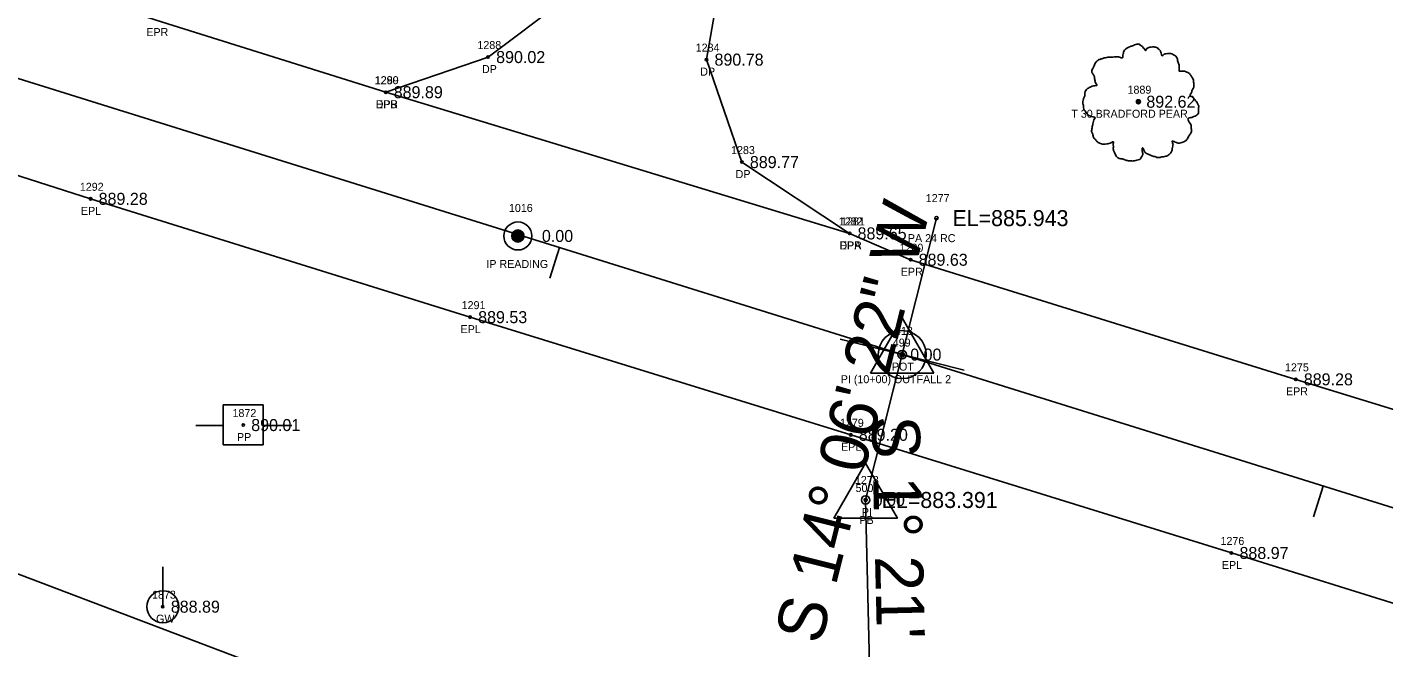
# Model space of a CAD drawing. Extents: x 1448136 to 1453623, y 1125056 to 1128842.
# Drawn here: x 1449466.4 to 1449636, y 1126782.3 to 1126859.8 of the extents above; entities that cross this region are included whole.
import ezdxf

# ---------------------------------------------------------------- set-up
doc = ezdxf.new("R2010")
doc.units = 0
for name, color, linetype in [('RD_EX_DR_Pipe', 7, 'Continuous'), ('RD_EX_DR_Pipe_txCode', 7, 'Continuous'), ('RD_EX_Driveway', 7, 'Continuous'), ('RD_EX_Driveway_txCode', 7, 'Continuous'), ('RD_EX_DV_Prop_txCode', 7, 'Continuous'), ('RD_EX_DV_PropPin', 7, 'Continuous'), ('RD_EX_Road', 7, 'Continuous'), ('RD_EX_Road_txCode', 7, 'Continuous'), ('RD_EX_TX_Driveway_ELEV', 7, 'Continuous'), ('RD_EX_TX_DV_Prop_ELEV', 7, 'Continuous'), ('RD_EX_TX_Road_ELEV', 7, 'Continuous'), ('RD_EX_TX_UT_ELEV', 7, 'Continuous'), ('RD_EX_TX_VEG_ELEV', 7, 'Continuous'), ('RD_EX_UT', 7, 'Continuous'), ('RD_EX_UT_txCode', 7, 'Continuous'), ('RD_EX_VEG', 7, 'Continuous'), ('RD_EX_VEG_txCode', 7, 'Continuous'), ('RD_HC_Cl', 7, 'Continuous'), ('RD_HC_Data', 7, 'Continuous'), ('RD_HC_Data_Tic', 7, 'Continuous'), ('RD_HC_Survey_ELEV', 7, 'Continuous'), ('RD_HC_txCode', 7, 'Continuous'), ('RD_SMD_Locator', 7, 'Continuous'), ('RD_TX_Pipe_ElevEX', 7, 'Continuous')]:
    doc.layers.add(name, color=color, linetype=linetype)

msp = doc.modelspace()

# ---------------------------------------------------------------- linework, layer by layer
at = {"layer": 'RD_EX_DR_Pipe'}
msp.add_line((1449580.07, 1126835.94), (1449571.22, 1126800.73), dxfattribs=at)
at = {"layer": 'RD_EX_Driveway'}
for points in [[(1449544.19, 1126877.39), (1449533.57, 1126863.24), (1449524.04, 1126856.06), (1449511.24, 1126851.67)], [(1449569.21, 1126834.03), (1449555.75, 1126842.94), (1449551.33, 1126855.74), (1449554.29, 1126872.78)]]:
    msp.add_lwpolyline(points, dxfattribs=at)
at = {"layer": 'RD_EX_DV_PropPin'}
for p, q in [((1449527.03, 1126833.51), (1449527.03, 1126833.9)), ((1449527.06, 1126833.41), (1449527.06, 1126834)), ((1449527.1, 1126833.34), (1449527.1, 1126834.08)), ((1449527.13, 1126833.28), (1449527.13, 1126834.13)), ((1449527.17, 1126833.23), (1449527.17, 1126834.18)), ((1449527.2, 1126833.19), (1449527.2, 1126834.22)), ((1449527.24, 1126833.16), (1449527.24, 1126834.26)), ((1449527.27, 1126833.12), (1449527.27, 1126834.29)), ((1449527.31, 1126833.1), (1449527.31, 1126834.32)), ((1449527.34, 1126833.07), (1449527.34, 1126834.34)), ((1449527.38, 1126833.05), (1449527.38, 1126834.36)), ((1449527.41, 1126833.03), (1449527.41, 1126834.38)), ((1449527.45, 1126833.01), (1449527.45, 1126834.4)), ((1449527.48, 1126833), (1449527.48, 1126834.41)), ((1449527.52, 1126832.99), (1449527.52, 1126834.43)), ((1449527.55, 1126832.98), (1449527.55, 1126834.44)), ((1449527.59, 1126832.97), (1449527.59, 1126834.45)), ((1449527.62, 1126832.96), (1449527.62, 1126834.46)), ((1449527.66, 1126832.95), (1449527.66, 1126834.46)), ((1449527.69, 1126832.95), (1449527.69, 1126834.46)), ((1449527.73, 1126832.95), (1449527.73, 1126834.47)), ((1449527.76, 1126832.95), (1449527.76, 1126834.47)), ((1449527.8, 1126832.95), (1449527.8, 1126834.47)), ((1449527.83, 1126832.95), (1449527.83, 1126834.46)), ((1449527.87, 1126832.95), (1449527.87, 1126834.46)), ((1449527.9, 1126832.96), (1449527.9, 1126834.46)), ((1449527.94, 1126832.97), (1449527.94, 1126834.45)), ((1449527.97, 1126832.98), (1449527.97, 1126834.44)), ((1449528.01, 1126832.99), (1449528.01, 1126834.43)), ((1449528.04, 1126833), (1449528.04, 1126834.41)), ((1449528.08, 1126833.01), (1449528.08, 1126834.4)), ((1449528.11, 1126833.03), (1449528.11, 1126834.38)), ((1449528.15, 1126833.05), (1449528.15, 1126834.36)), ((1449528.18, 1126833.07), (1449528.18, 1126834.34)), ((1449528.22, 1126833.1), (1449528.22, 1126834.32)), ((1449528.25, 1126833.12), (1449528.25, 1126834.29)), ((1449528.29, 1126833.16), (1449528.29, 1126834.26)), ((1449528.32, 1126833.19), (1449528.32, 1126834.22)), ((1449528.36, 1126833.23), (1449528.36, 1126834.18)), ((1449528.39, 1126833.28), (1449528.39, 1126834.13)), ((1449528.43, 1126833.34), (1449528.43, 1126834.08)), ((1449528.46, 1126833.41), (1449528.46, 1126834)), ((1449528.5, 1126833.51), (1449528.5, 1126833.9))]:
    msp.add_line(p, q, dxfattribs=at)
for radius in [1.75, 0.761]:
    msp.add_circle((1449527.76, 1126833.71), radius, dxfattribs=at)
at = {"layer": 'RD_EX_Road'}
for points in [[(1450334.81, 1126677.22), (1450288.34, 1126667.77), (1450239.92, 1126662.52), (1450192.72, 1126661.45), (1450145.26, 1126665.09), (1450097.34, 1126672.81), (1450049.7, 1126684.25), (1450007.41, 1126696.7), (1449955.88, 1126712.65), (1449909.23, 1126727.21), (1449862.31, 1126741.85), (1449813.73, 1126756.84), (1449766.18, 1126771.72), (1449717.33, 1126787.19), (1449671.79, 1126801.4), (1449624.98, 1126815.8), (1449576.84, 1126830.74), (1449569.21, 1126834.03), (1449511.24, 1126851.67), (1449482.54, 1126860.68), (1449432.31, 1126877.02)], [(1450340.73, 1126655.01), (1450291.74, 1126645.33), (1450242.07, 1126639.91), (1450191.92, 1126637.95), (1450184.99, 1126636.16), (1450163.38, 1126634.92), (1450141.93, 1126638.08), (1450123.3, 1126641.98), (1450121.61, 1126644.88), (1450093.17, 1126650), (1450044.99, 1126661.93), (1449996.8, 1126675.54), (1449949.24, 1126690.23), (1449901.53, 1126705.51), (1449854.27, 1126720.01), (1449807.04, 1126735.02), (1449759.58, 1126749.86), (1449712.08, 1126764.7), (1449664.51, 1126779.32), (1449616.94, 1126794.11), (1449569.36, 1126808.87), (1449521.79, 1126823.57), (1449474.36, 1126838.35), (1449426.72, 1126853.6)]]:
    msp.add_lwpolyline(points, dxfattribs=at)
at = {"layer": 'RD_EX_UT'}
for p, q in [((1449495.93, 1126812.6), (1449490.93, 1126812.6)), ((1449490.93, 1126812.6), (1449490.93, 1126807.6)), ((1449495.93, 1126807.6), (1449495.93, 1126812.6)), ((1449487.49, 1126810.04), (1449490.96, 1126810.04)), ((1449495.85, 1126810.04), (1449499.49, 1126810.04)), ((1449490.93, 1126807.6), (1449495.93, 1126807.6)), ((1449483.38, 1126787.4), (1449483.38, 1126792.4))]:
    msp.add_line(p, q, dxfattribs=at)
msp.add_circle((1449483.38, 1126787.4), 2, dxfattribs=at)
at = {"layer": 'RD_EX_VEG'}
msp.add_lwpolyline([(1449580.16, 1126756.85), (1449515.49, 1126772.44), (1449452.16, 1126796.48), (1449411.7, 1126813.35), (1449361.89, 1126826.23), (1449322.6, 1126840.71), (1449267.19, 1126862.08), (1449183.91, 1126901.45), (1449150.59, 1126885.87), (1449094.51, 1126880.74), (1449046.23, 1126869.03), (1449021.78, 1126857.03), (1449018.91, 1126811.39)], dxfattribs=at)
for centre, radius in [((1449605.3, 1126850.48), 0.25), ((1449605.29, 1126850.46), 0.0001)]:
    msp.add_circle(centre, radius, dxfattribs=at)
for points in [[(1449605.43, 1126857.65), (1449605.13, 1126857.67), (1449604.81, 1126857.57), (1449604.56, 1126857.47), (1449604.33, 1126857.4), (1449604.11, 1126857.3), (1449603.81, 1126857.12), (1449603.58, 1126856.92), (1449603.46, 1126856.67), (1449603.41, 1126856.45), (1449603.36, 1126856.17), (1449603.36, 1126856), (1449603.23, 1126855.97), (1449603.08, 1126856), (1449602.83, 1126856.07), (1449602.58, 1126856.07), (1449602.33, 1126856.07), (1449601.98, 1126856.05), (1449601.63, 1126856.05), (1449601.36, 1126856), (1449601.03, 1126855.95), (1449600.66, 1126855.82), (1449600.31, 1126855.7), (1449600.01, 1126855.45), (1449599.76, 1126854.97), (1449599.63, 1126854.62), (1449599.48, 1126854.37), (1449599.63, 1126853.92), (1449599.81, 1126853.57), (1449599.83, 1126853.37), (1449599.91, 1126852.95), (1449600.01, 1126852.72), (1449600.13, 1126852.52), (1449600.06, 1126852.5), (1449599.68, 1126852.45), (1449599.38, 1126852.35), (1449598.96, 1126852.12), (1449598.73, 1126851.9), (1449598.63, 1126851.57), (1449598.61, 1126851.23), (1449598.51, 1126851.03), (1449598.43, 1126850.75), (1449598.41, 1126850.68), (1449598.36, 1126850.35), (1449598.46, 1126849.9), (1449598.48, 1126849.55), (1449598.61, 1126849.33), (1449598.76, 1126849.15), (1449598.93, 1126848.9), (1449599.33, 1126848.68), (1449599.66, 1126848.58), (1449599.86, 1126848.55), (1449599.68, 1126848.05), (1449599.63, 1126847.7), (1449599.51, 1126847.3), (1449599.51, 1126847.23), (1449599.46, 1126846.75), (1449599.61, 1126846.43), (1449599.68, 1126846.05), (1449599.86, 1126845.83), (1449600.13, 1126845.53), (1449600.46, 1126845.3), (1449600.96, 1126845.18), (1449601.36, 1126845.2), (1449601.93, 1126845.38), (1449602.18, 1126845.45), (1449602.16, 1126845.28), (1449602.18, 1126844.9), (1449602.18, 1126844.48), (1449602.33, 1126844.15), (1449602.43, 1126843.88), (1449602.58, 1126843.63), (1449602.91, 1126843.4), (1449603.31, 1126843.33), (1449603.73, 1126843.18), (1449604.18, 1126843.1), (1449604.68, 1126843.08), (1449605.28, 1126843.23), (1449605.56, 1126843.35), (1449605.66, 1126843.53), (1449605.86, 1126843.9), (1449605.81, 1126844.13), (1449605.83, 1126844.73), (1449605.93, 1126844.55), (1449606.11, 1126844.2), (1449606.6, 1126843.9), (1449607, 1126843.73), (1449607.48, 1126843.58), (1449607.78, 1126843.5), (1449608.25, 1126843.58), (1449608.63, 1126843.65), (1449609, 1126843.78), (1449609.3, 1126844.05), (1449609.48, 1126844.33), (1449609.53, 1126844.6), (1449609.6, 1126844.98), (1449609.65, 1126845.15)], [(1449609.65, 1126845.15), (1449609.58, 1126845.33), (1449609.53, 1126845.58), (1449609.6, 1126845.55), (1449609.78, 1126845.5), (1449610.05, 1126845.38), (1449610.28, 1126845.3), (1449610.6, 1126845.33), (1449610.88, 1126845.43), (1449611.33, 1126845.7), (1449611.6, 1126846.18), (1449611.88, 1126846.58), (1449611.95, 1126846.9), (1449611.9, 1126847.13), (1449611.88, 1126847.63), (1449611.68, 1126847.88), (1449611.63, 1126848), (1449611.53, 1126848.4), (1449611.6, 1126848.45), (1449611.88, 1126848.5), (1449612.25, 1126848.63), (1449612.53, 1126848.75), (1449612.75, 1126848.93), (1449612.83, 1126849.15), (1449612.8, 1126849.55), (1449612.85, 1126849.95), (1449612.78, 1126850.1), (1449612.68, 1126850.25), (1449612.6, 1126850.45), (1449612.45, 1126850.6), (1449612.35, 1126850.75), (1449612.25, 1126850.85), (1449612.13, 1126851), (1449611.95, 1126851.13), (1449611.8, 1126851.18), (1449611.75, 1126851.33), (1449611.9, 1126851.53), (1449611.95, 1126851.62), (1449611.98, 1126851.85), (1449612.2, 1126852.2), (1449612.25, 1126852.6), (1449612.2, 1126853.02), (1449612.15, 1126853.3), (1449612, 1126853.57), (1449611.8, 1126853.82), (1449611.68, 1126854), (1449611.5, 1126854.12), (1449611.18, 1126854.25), (1449610.93, 1126854.3), (1449610.58, 1126854.3), (1449610.38, 1126854.35), (1449610.4, 1126854.4), (1449610.4, 1126854.55), (1449610.4, 1126854.82), (1449610.33, 1126855.27), (1449610.18, 1126855.77), (1449610.18, 1126855.8), (1449610.08, 1126856.05), (1449609.85, 1126856.25), (1449609.68, 1126856.35), (1449609.48, 1126856.47), (1449609.23, 1126856.5), (1449608.93, 1126856.5), (1449608.65, 1126856.45), (1449608.45, 1126856.35), (1449608.28, 1126856.22), (1449608.2, 1126856.37), (1449608.1, 1126856.67), (1449608.05, 1126856.82), (1449607.9, 1126857), (1449607.68, 1126857.2), (1449607.23, 1126857.32), (1449606.6, 1126857.25), (1449606.31, 1126857.05), (1449606.16, 1126856.87), (1449606.11, 1126857), (1449605.91, 1126857.2), (1449605.81, 1126857.37), (1449605.63, 1126857.5), (1449605.48, 1126857.6), (1449605.38, 1126857.65)]]:
    msp.add_spline(points, degree=3, dxfattribs=at)
at = {"layer": 'RD_HC_Cl'}
for p, q in [((1450033.34, 1126676.03), (1449295.29, 1126906.46)), ((1449575.79, 1126818.89), (1449571.22, 1126800.73)), ((1449571.22, 1126800.73), (1449571.88, 1126772.92))]:
    msp.add_line(p, q, dxfattribs=at)
at = {"layer": 'RD_HC_Data'}
for p, q in [((1449571.82, 1126816.59), (1449575.79, 1126823.47)), ((1449575.79, 1126823.47), (1449579.76, 1126816.59)), ((1449571.82, 1126816.59), (1449579.76, 1126816.59)), ((1449567.25, 1126798.44), (1449571.22, 1126805.32)), ((1449571.22, 1126805.32), (1449575.19, 1126798.44)), ((1449567.25, 1126798.44), (1449575.19, 1126798.44))]:
    msp.add_line(p, q, dxfattribs=at)
for centre, radius in [((1449575.79, 1126818.89), 3), ((1449575.79, 1126818.89), 0.529), ((1449575.79, 1126818.89), 0.282), ((1449571.22, 1126800.73), 0.529)]:
    msp.add_circle(centre, radius, dxfattribs=at)
at = {"layer": 'RD_HC_Data_Tic'}
for p, q in [((1449532.94, 1126832.26), (1449531.75, 1126828.45)), ((1449575.79, 1126818.89), (1449568.03, 1126820.84)), ((1449575.79, 1126818.89), (1449583.55, 1126816.94)), ((1449628.4, 1126802.46), (1449627.2, 1126798.64))]:
    msp.add_line(p, q, dxfattribs=at)
at = {"layer": 'RD_SMD_Locator'}
for centre, radius in [((1449524.04, 1126856.06), 0.15), ((1449551.33, 1126855.74), 0.15), ((1449511.24, 1126851.67), 0.15), ((1449511.24, 1126851.67), 0.15), ((1449605.3, 1126850.48), 0.15), ((1449555.75, 1126842.94), 0.15), ((1449474.36, 1126838.35), 0.15), ((1449580.07, 1126835.94), 0.2), ((1449527.76, 1126833.71), 0.15), ((1449569.21, 1126834.03), 0.15), ((1449569.21, 1126834.03), 0.15), ((1449576.84, 1126830.74), 0.15), ((1449521.79, 1126823.57), 0.15), ((1449575.79, 1126818.89), 0.15), ((1449575.79, 1126818.89), 0.15), ((1449624.98, 1126815.8), 0.15), ((1449493.43, 1126810.09), 0.15), ((1449569.36, 1126808.87), 0.15), ((1449571.22, 1126800.73), 0.2), ((1449571.22, 1126800.73), 0.15), ((1449616.94, 1126794.11), 0.15), ((1449483.38, 1126787.4), 0.15)]:
    msp.add_circle(centre, radius, dxfattribs=at)

# ---------------------------------------------------------------- texts
at = {"layer": 'RD_EX_DR_Pipe_txCode'}
for s, p in [('1277', (1449578.73, 1126837.94)), ('PA 24 RC', (1449576.5, 1126832.94)), ('1278', (1449569.88, 1126802.73)), ('PB', (1449570.44, 1126797.73))]:
    msp.add_text(s, height=1, dxfattribs=at).set_placement(p)
at = {"layer": 'RD_EX_Driveway_txCode'}
for s, p in [('1288', (1449522.7, 1126857.06)), ('1284', (1449549.98, 1126856.74)), ('DP', (1449523.27, 1126854.06)), ('1289', (1449509.89, 1126852.67)), ('DP', (1449550.55, 1126853.74)), ('DPB', (1449509.99, 1126849.67)), ('1283', (1449554.4, 1126843.94)), ('DP', (1449554.97, 1126840.94)), ('1282', (1449567.86, 1126835.03)), ('DPA', (1449567.94, 1126832.03))]:
    msp.add_text(s, height=1, dxfattribs=at).set_placement(p)
at = {"layer": 'RD_EX_DV_Prop_txCode'}
for s, p in [('1016', (1449526.64, 1126836.71)), ('IP READING', (1449523.82, 1126829.71))]:
    msp.add_text(s, height=1, dxfattribs=at).set_placement(p)
at = {"layer": 'RD_EX_Road_txCode'}
for s, p in [('EPR', (1449481.32, 1126858.68)), ('1290', (1449509.86, 1126852.67)), ('EPR', (1449510.01, 1126849.67)), ('1292', (1449473.01, 1126839.35)), ('EPL', (1449473.15, 1126836.35)), ('1281', (1449568.15, 1126835.03)), ('EPR', (1449567.98, 1126832.03)), ('1280', (1449575.45, 1126831.74)), ('EPR', (1449575.61, 1126828.74)), ('1291', (1449520.73, 1126824.57)), ('EPL', (1449520.59, 1126821.57)), ('1275', (1449623.63, 1126816.8)), ('EPR', (1449623.75, 1126813.8)), ('1279', (1449568.01, 1126809.87)), ('EPL', (1449568.15, 1126806.87)), ('1276', (1449615.57, 1126795.11)), ('EPL', (1449615.74, 1126792.11))]:
    msp.add_text(s, height=1, dxfattribs=at).set_placement(p)
at = {"layer": 'RD_EX_TX_Driveway_ELEV'}
for s, p in [('890.02', (1449525.04, 1126855.31)), ('890.78', (1449552.33, 1126854.99)), ('889.89', (1449512.24, 1126850.92)), ('889.77', (1449556.75, 1126842.19)), ('889.65', (1449570.21, 1126833.28))]:
    msp.add_text(s, height=1.5, dxfattribs=at).set_placement(p)
at = {"layer": 'RD_EX_TX_DV_Prop_ELEV'}
msp.add_text('0.00', height=1.5, dxfattribs=at).set_placement((1449530.76, 1126832.96))
at = {"layer": 'RD_EX_TX_Road_ELEV'}
for s, p in [('889.89', (1449512.24, 1126850.92)), ('889.28', (1449475.36, 1126837.6)), ('889.65', (1449570.21, 1126833.28)), ('889.63', (1449577.84, 1126829.99)), ('889.53', (1449522.79, 1126822.82)), ('889.28', (1449625.98, 1126815.05)), ('889.20', (1449570.36, 1126808.12)), ('888.97', (1449617.94, 1126793.36))]:
    msp.add_text(s, height=1.5, dxfattribs=at).set_placement(p)
at = {"layer": 'RD_EX_TX_UT_ELEV'}
msp.add_text('888.89', height=1.5, dxfattribs=at).set_placement((1449484.38, 1126786.65))
at = {"layer": 'RD_EX_TX_VEG_ELEV'}
msp.add_text('892.62', height=1.5, dxfattribs=at).set_placement((1449606.3, 1126849.73))
at = {"layer": 'RD_EX_UT_txCode'}
for s, p in [('1872', (1449492.09, 1126811.09)), ('PP', (1449492.65, 1126808.09)), ('1873', (1449482.04, 1126788.4)), ('GW', (1449482.54, 1126785.4))]:
    msp.add_text(s, height=1, dxfattribs=at).set_placement(p)
at = {"layer": 'RD_EX_VEG_txCode'}
for s, p in [('1889', (1449603.95, 1126851.48)), ('T 30 BRADFORD PEAR', (1449596.92, 1126848.48))]:
    msp.add_text(s, height=1, dxfattribs=at).set_placement(p)
at = {"layer": 'RD_HC_Data'}
for s, rotation, p in [('S 14%%d 06\' 22" W', 75.8939, (1449565.62, 1126782.54)), ('S 1%%d 21\' 46" E', 271.3628, (1449571.97, 1126811.19))]:
    msp.add_text(s, height=6, rotation=rotation, dxfattribs=at).set_placement(p)
at = {"layer": 'RD_HC_Survey_ELEV'}
for s, p in [('0.00', (1449576.79, 1126818.14)), ('0.00', (1449576.79, 1126818.14)), ('890.01', (1449494.43, 1126809.34)), ('0.00', (1449572.22, 1126799.98))]:
    msp.add_text(s, height=1.5, dxfattribs=at).set_placement(p)
at = {"layer": 'RD_HC_txCode'}
for s, p in [('413', (1449574.89, 1126821.36)), ('499', (1449574.61, 1126819.89)), ('POT', (1449574.5, 1126816.89)), ('PI (10+00) OUTFALL 2', (1449568.11, 1126815.32)), ('500', (1449569.96, 1126801.73)), ('PI', (1449570.75, 1126798.73))]:
    msp.add_text(s, height=1, dxfattribs=at).set_placement(p)
at = {"layer": 'RD_TX_Pipe_ElevEX'}
for s, p in [('EL=885.943', (1449582.07, 1126834.94)), ('EL=883.391', (1449573.22, 1126799.73))]:
    msp.add_text(s, height=2, dxfattribs=at).set_placement(p)

doc.saveas('drawing.dxf')
